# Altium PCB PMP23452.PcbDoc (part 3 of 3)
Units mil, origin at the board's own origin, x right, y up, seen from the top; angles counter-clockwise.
Board outline 4000 x 4000 mil, 6 copper layers (Top Layer, Layer 2, Layer 3, Layer 4, Layer 5, Bottom Layer), stack 40.224 mil thick; 235 components, 68 nets, 526 pads, 358 vias.
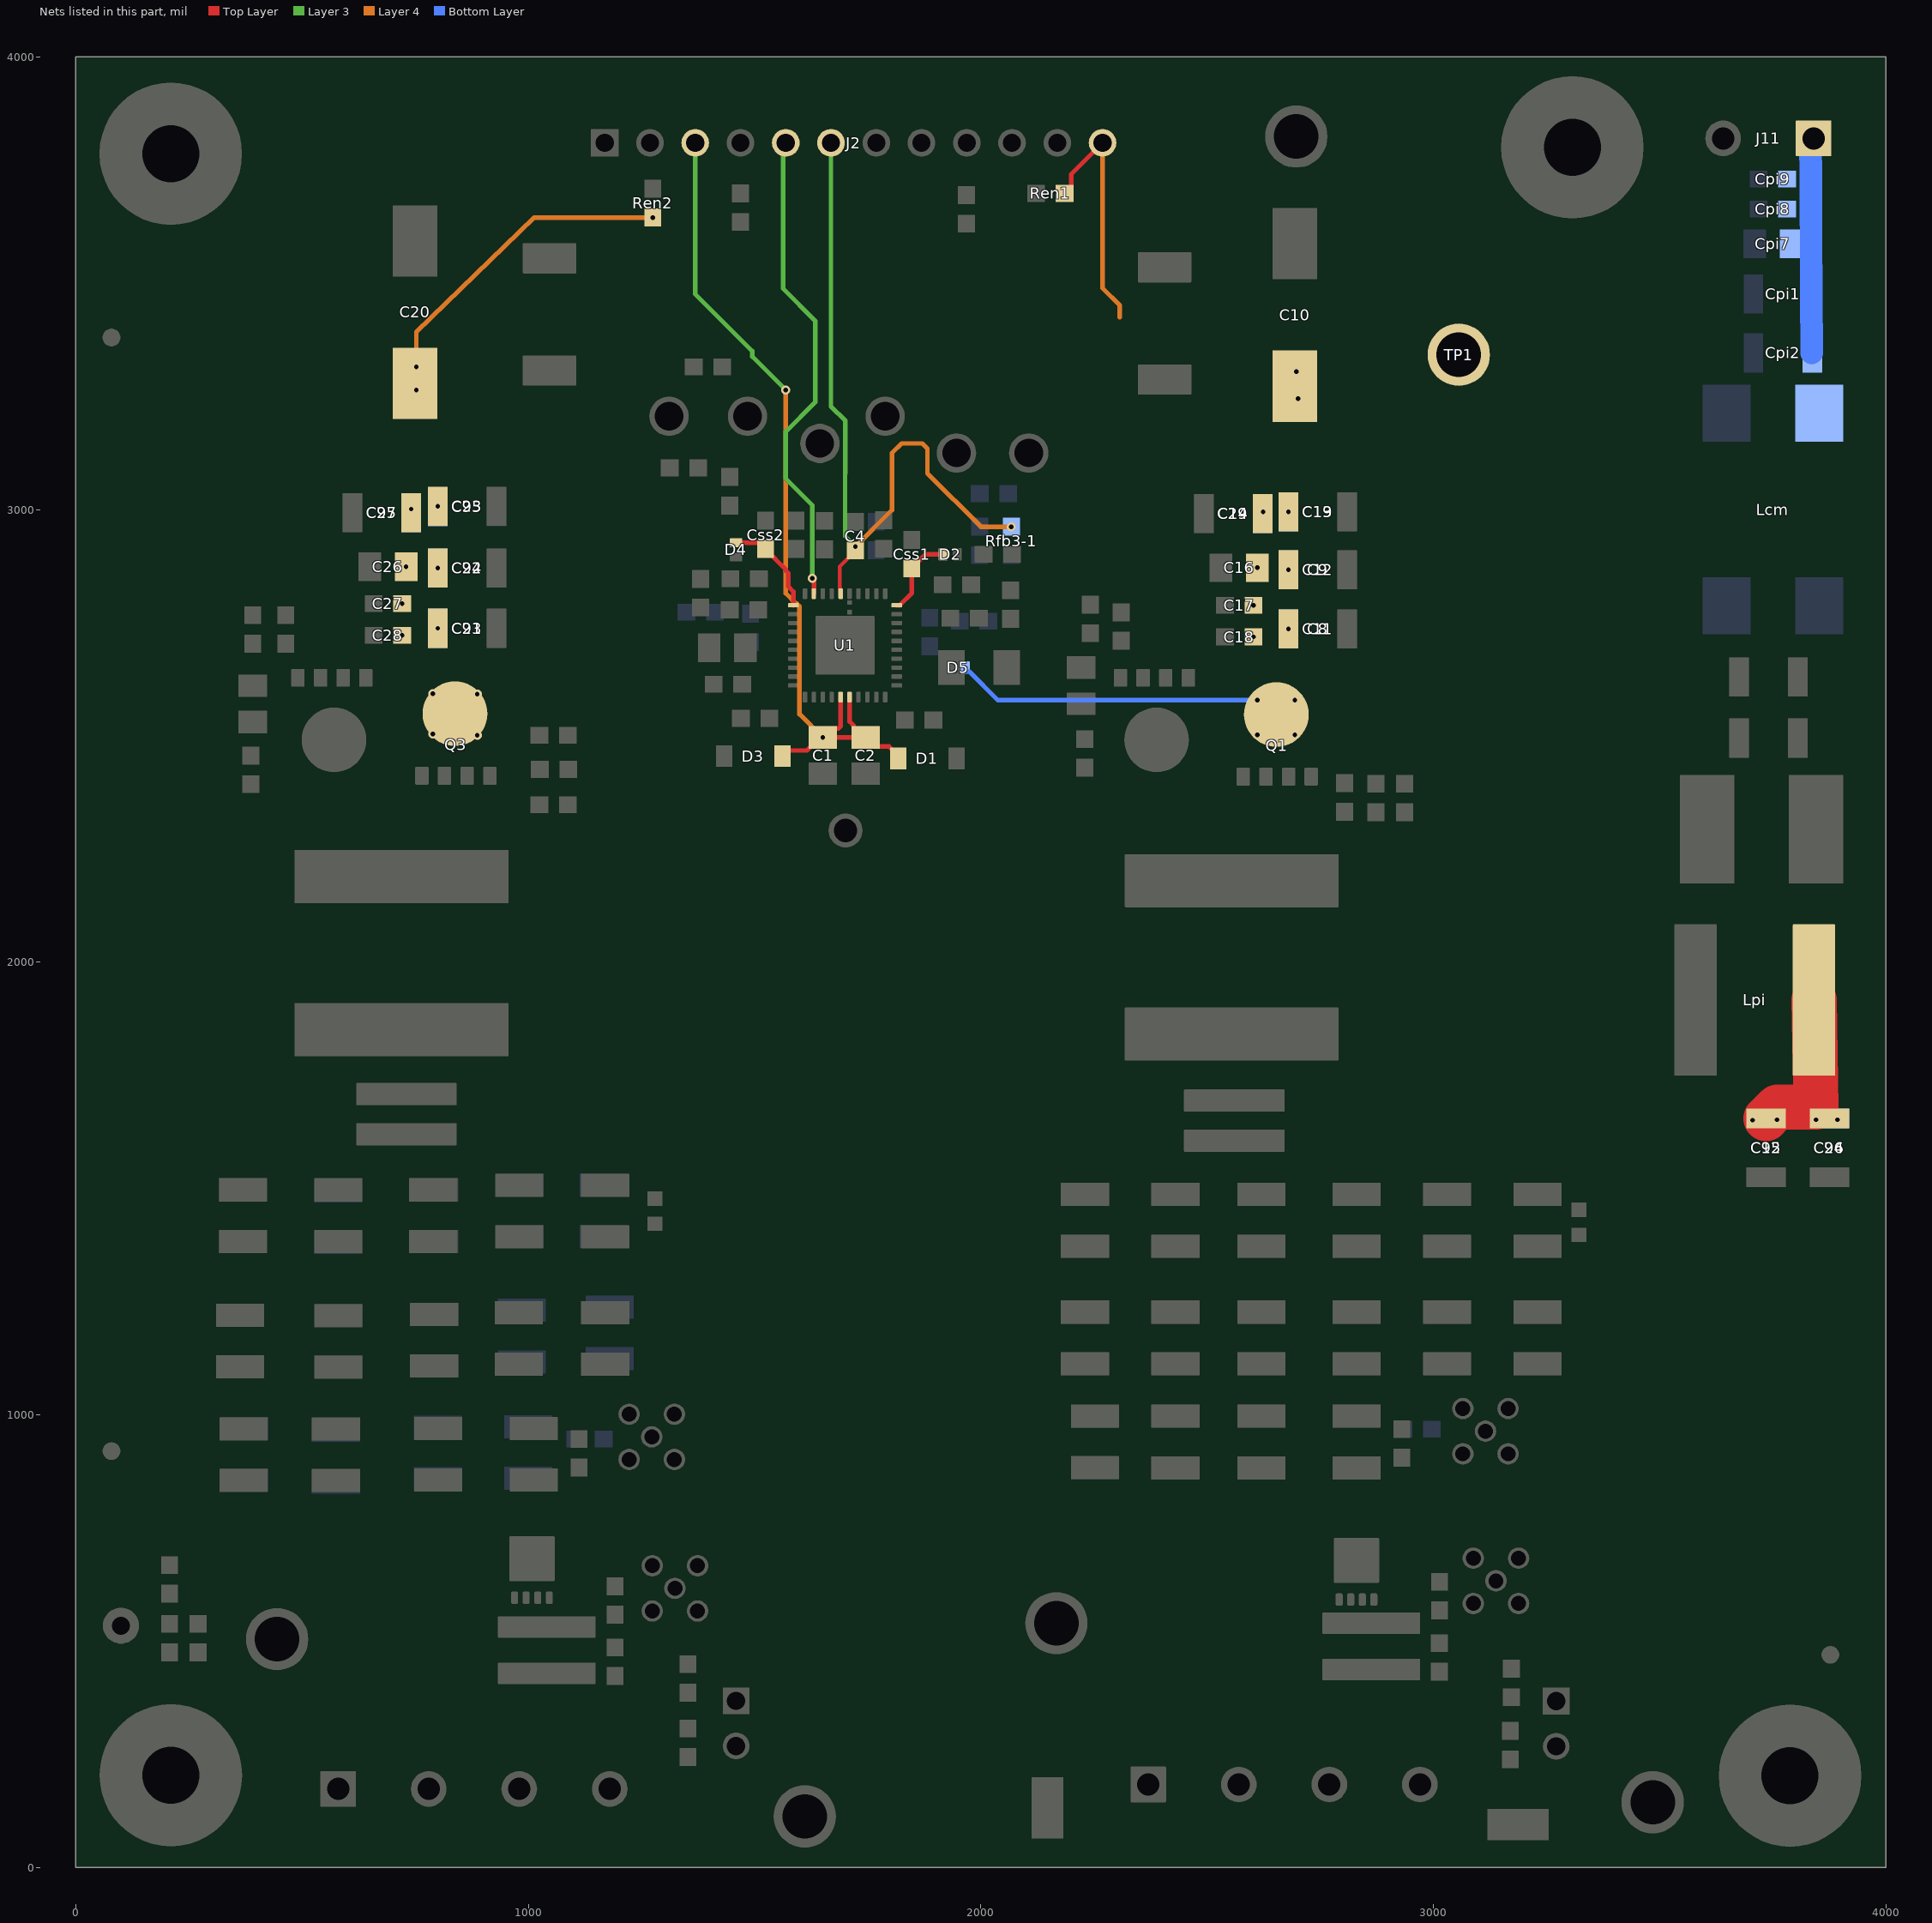
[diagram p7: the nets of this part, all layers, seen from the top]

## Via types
v1: diameter 20, hole 10, Top Layer to Bottom Layer, tented both sides, 332 vias
v2: diameter 19.68, hole 7.87, Top Layer to Bottom Layer, 24 vias
v3: diameter 19.68, hole 7.87, Top Layer to Bottom Layer, tented both sides, 2 vias

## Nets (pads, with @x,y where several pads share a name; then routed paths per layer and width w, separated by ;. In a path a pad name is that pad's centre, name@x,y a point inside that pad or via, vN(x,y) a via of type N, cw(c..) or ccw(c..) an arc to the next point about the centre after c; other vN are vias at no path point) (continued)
SS1: Css1.1 D2.1 U1.30 | length 181.6
  Top Layer w10: U1.30@1814.17,2788.58 1820.91,2788.58 1847.49,2815.17 Css1.1@1847.49,2869.76 1847.49,2870.74 1878.01,2901.25 D2.1@1916.5,2901.25
SS2: Css2.1 D4.1 U1.1 | length 220.9
  Top Layer w10: D4.1@1459.2,2926.84 1510.77,2926.84 1524.47,2913.14 Css2.1@1524.47,2912.71 1524.47,2911.73 1568.9,2867.29 1568.9,2865.31 1574.68,2859.53 1574.68,2829.67 1585.83,2818.52 U1.1@1585.83,2788.58
SYNCOUT: J2.5 U1.39 | length 1080.4
  Top Layer w10: v1(1627.52,2848.07) 1627.52,2845.37 1631.1,2841.79 U1.39@1631.1,2814.17
  Layer 3 w10: J2.5@1568.9,3810 1563,3804.1 1563,3488 1634,3417 1634,3237 1568.9,3171.9 1568.9,3068.36 1627.52,3009.73 v1(1627.52,2848.07)
VCC: C1.1 C2.1 D1.2 D3.2 J2.3 U1.15 U1.16 | length 1942.2
  Top Layer w10: D3.2@1561.67,2455.34 1574.01,2467.68 1615.51,2467.68 1644.29,2496.46 v1(1650.79,2496.46) ; U1.15@1690.16,2585.83 1690.16,2520.67 1685.95,2516.46 1670.79,2516.46 v1(1650.79,2496.46) ; U1.16@1709.84,2585.83 1709.84,2531.89 1718.78,2522.96 1718.78,2516.46 C2.1@1738.78,2496.46 ; D1.2@1817.2,2450.45 1817.2,2456.46 1797.2,2476.46 1765.28,2476.46 C2.1@1745.28,2496.46 C2.1@1738.78,2496.46 ; v1(1650.79,2496.46) C2.1@1738.78,2496.46
  Layer 3 w10: J2.3@1368.9,3810 1368.9,3476.02 1495,3349.92 1495,3338.02 v1(1568.9,3264.13)
  Layer 4 w10: v1(1568.9,3264.13) 1568.9,2815.08 1591.97,2792.01 1593.49,2792.01 1599.34,2786.15 1599.34,2547.9 v1(1650.79,2496.46)
VDDA: C4.2 J2.6 Rfb3-1.2 U1.36 | length 1646.2
  Top Layer w8: U1.36@1690.16,2814.17 1689.24,2815.09 1689.24,2827.03 1688.28,2827.98 1688.28,2874.36 C4.2@1722.64,2908.72
  Top Layer w10: C4.2@1722.64,2908.72 C4.2@1722.64,2909.7
  Layer 3 w10: J2.6@1668.9,3810 1668.9,3227.69 1700.66,3195.93 1700.66,3080.02 1700,3079.36 1700,2940.83 v1(1722.87,2917.96)
  Layer 4 w10: v1(1722.87,2917.96) 1803.81,2998.89 1803.81,3124.96 1824.85,3146 1870.6,3146 1882,3134.6 1882,3080 2000,2962 v1(2067,2962)
VIN: C8.1 C9.1 C10.1 C11.1 C12.1 C13.1 C14.1 C15.1 C16.1 C17.1 C18.1 C19.1 C20.1 C21.1 C22.1 C23.1 C24.1 C25.1 C26.1 C27.1 C28.1 C29.1 C92.1 C93.1 C94.1 C95.1 C96.1 C97.1 D5.2 J2.12 Lpi.2 Q1.5-6 Q3.5-6 Ren1.2 Ren2.2 TP1.1 | length 2284.2
  Top Layer w10: Ren1.2@2185,3698.5 2185.98,3698.5 2199.69,3712.2 2199.69,3740.79 J2.12@2268.9,3810
  Top Layer w100: C15.1@3735,1654.96 3760.04,1680 3845.47,1680 Lpi.2@3840.91,1916.5
  Layer 4 w10: v1(752.49,3315.13) 752.49,3392.49 1013,3645 v1(1275,3645) ; J2.12@2268.9,3810 2268.9,3489.1 2307,3451 2307,3425
  Bottom Layer w10: D5.2@1965.72,2650.87 1965.72,2646.93 1970.56,2642.09 1974.49,2642.09 2037.49,2579.09 v1(2610.71,2579.09)
  other v1: 3705,1651 3759,1652 3845.47,1652 3892.85,1652 887.24,2501.34 2610.71,2502.22 2693.94,2502.22 789,2504.06 2693.94,2579.09 887.24,2592.35 789,2593 2602.21,2718.7 721.5,2722.01 2679.65,2736.17 800.04,2737.49 2602.21,2788.58 721.5,2792.01 2679.65,2867.25 800.04,2870.74 2610.71,2871.5 730,2873.5 2623.85,2994.88 2679.65,2994.88 741.2,3001.18 800.04,3007.32 2700.75,3245 752.49,3264.13 2697,3304.44
VIN-ext: Cpi1.1 Cpi2.1 Cpi7.1 Cpi8.1 Cpi9.1 J11.1 Lcm.1 | length 479
  Bottom Layer w50: J11.1@3831,3832 J11.1@3831.08,3819.94 ; J11.1@3833.08,3812.94 3833.62,3729 3834.02,3667.54 3834.56,3585.71 3835.13,3496.99 3835.27,3475.99 Cpi2.1@3836.12,3345.99
pads on no net: FID1.1 FID2.1 FID3.1 H3.0 H4.0 H5.0 H6.0 H7.1 H8.1 H9.1 H10.1 Q100.9A Q100.9B Q100.9C Q100.9D Q200.9A Q200.9B Q200.9C Q200.9D

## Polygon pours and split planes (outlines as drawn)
VIN on Top Layer "TOP_LAYER_VIN_P000" (solid, remove dead copper, pour order 0): 2633.94,3367.93 2756.94,3367.93 2756.94,3077.09 2729.84,3050 2729.84,2687.43 2764.28,2653 2764.28,2464.05 2547.54,2464.05 2540.28,2471.32 2550.66,2481.7 2550.66,2660.44 2555.03,2660.44 2584.77,2690.18 2584.77,3054.77 2637.99,3108 2633.94,3112.05 2633.94,3371.26
VIN on Top Layer "TOP_LAYER_VIN_P005" (solid, remove dead copper, pour order 5): 670.53,3367.68 815,3367.68 815,3097.72 855,3057.72 855,2681.46 896.38,2640.08 947.28,2640.08 947.28,2475.28 944.18,2472.18 942.01,2474.36 729.84,2474.36 729.84,2656.3 735.82,2662.27 699.01,2699.08 699.01,2925 686.04,2937.97 676.24,2937.97 676.24,3361.97
5V on Top Layer "TOP_LAYER_5V_P009" (solid, remove dead copper, pour order 9): 290,1655 294,1659 1324,1659 1324,920.39 1040.91,637.3 904.36,545.31 904.36,41 400.05,41 400.05,685 288,685 286,683 286,1655
PGND on Top Layer "TOP_LAYER_PGND_P029" (solid, remove dead copper, pour order 29): 20,3980 20,20 3980,20 3980,3000 3500,3000 3500,3980
NetCpi3_1 on Top Layer "TOP_LAYER_NETCPI3_1_P028" (solid, remove dead copper, pour order 28): 3898.37,2695 3750.86,2695 3750,2694.14 3750,2170 3898.37,2170
NetC102_2 on Top Layer "TOP_LAYER_NETC102_2_P020" (solid, remove dead copper, pour order 20): 2720,623.66 2720,495.5 2956.56,495.5 2988.05,464.01 3037.89,464.01 3040.4,461.5 3040.4,599.88 2986.23,599.88 2964.87,578.52 2855.59,578.52 2855.59,623.66
NetC6_1 on Top Layer "TOP_LAYER_NETC6_1_P017" (solid, remove dead copper, pour order 17): 2282.74,2123 2286.74,2127 2803.74,2127 2803.74,2266.87 2711.99,2358.63 2711.99,2450.45 2526.63,2450.45 2521.74,2455.34 2530.29,2463.88 2530.29,2579.09 2281.98,2579.09 2265.22,2562.33 2265.22,2139.53 2282.74,2122
NetL1_1 on Top Layer "TOP_LAYER_NETL1_1_P012" (solid, remove dead copper, pour order 12): 2304.84,1914.5 2294.94,1904.59 2294.94,1755.41 2391.47,1658.87 2757.54,1658.87 2807.84,1709.18 2807.84,1916.5 2310.34,1916.5 2307.34,1913.5
3.3V on Top Layer "TOP_LAYER_3.3V_P011" (solid, remove dead copper, pour order 11): 2166.72,1648.5 2170.72,1652.5 3373,1652.5 3373,1086.17 2917.64,630.81 2700,630.81 2700,34.5 2052,34.5 2052,565.78 2052,1648.5
NetC202_2 on Top Layer "TOP_LAYER_NETC202_2_P010" (solid, remove dead copper, pour order 10): 950.84,616.8 950.84,576.78 936.58,576.78 918.28,558.48 918.28,488.63 1134.61,488.63 1166.1,457.14 1215.94,457.14 1218.45,454.63 1218.45,593.01 1164.28,593.01 1142.92,571.65 1025.97,571.65 1025.97,616.8 950.28,616.8
AGND on Top Layer "TOP_LAYER_AGND_P006" (solid, remove dead copper, pour order 6): 1349.68,2815.17 1471.01,2815.17 1471.01,2869.55 1472.2,2870.74 1468.62,2874.32 1430.9,2874.32 1430.9,2941.86 1432.74,2943.7 1434.67,2941.77 1808.27,2941.77 1808.27,2935.78 1820.91,2923.14 1820.91,2897.32 1824.84,2901.25 1895.29,2901.25 1895.29,2920.43 1916.62,2941.77 1968.9,2941.77 1968.9,2870.74 1949.97,2851.81 1949.97,2797.68 1952.92,2794.73 2117.91,2794.73 2117.91,2857.6 2105.76,2869.76 2038.23,2869.76 2038.23,3162.47 1960.81,3295.16 1235,3365 1337.18,2814.09 1329.88,2806.8 1329.88,2802.11 1329.88,2810.92 1327.81,2808.86
NetL2_2 on Top Layer "TOP_LAYER_NETL2_2_P008" (solid, remove dead copper, pour order 8): 474,1915 464.09,1905.09 464.09,1755.91 560.63,1659.37 926.69,1659.37 977,1709.68 977,1917 479.5,1917 476.5,1914
NetC7_1 on Top Layer "TOP_LAYER_NETC7_1_P007" (solid, remove dead copper, pour order 7): 458,2123 462,2127 979,2127 979,2266.87 887.24,2358.63 887.24,2450.45 701.89,2450.45 697,2455.34 705.54,2463.88 705.54,2579.09 457.24,2579.09 440.47,2562.33 440.47,2139.53 458,2122
AGND on Layer 2 "LAYER_2_AGND_P002" (solid, remove dead copper, pour order 2): 1595.4,3186.91 1595.4,2965.95 1803.81,2965.95 1811.23,2973.37 1811.23,3246.48 1654.96,3246.48
PGND on Layer 2 "LAYER_2_PGND_P036" (solid, remove dead copper, pour order 36): 20,3980 20,20 3980,20 3980,3000 3500,3000 3500,3980
AGND on Layer 2 "LAYER_2_AGND_P001" (solid, remove dead copper, pour order 1): 1368.9,3025.47 1463.53,3025.47 1495,2994 1826.58,2994 2007,2958 2060.18,2857.44 2060.18,2846.9 2027.43,2810.44 1368.9,2810.44
VIN on Bottom Layer "BOTTOM_LAYER_VIN_P015" (solid, remove dead copper, pour order 15): 823,3367.68 823,2777.48 949.25,2470.06 758.7,2470.06 703.08,2698 705.54,2700.47 705.54,3367.68
VIN on Bottom Layer "BOTTOM_LAYER_VIN_P016" (solid, remove dead copper, pour order 16): 2721.01,3363.95 2721.01,2476.51 2586.71,2476.51 2586.71,3363.95
PGND on Bottom Layer "BOTTOM_LAYER_PGND_P031" (solid, remove dead copper, pour order 31): 20,3980 20,20 3980,20 3980,3000 3500,3000 3500,3980
NetCpi3_1 on Bottom Layer "BOTTOM_LAYER_NETCPI3_1_P030" (solid, remove dead copper, pour order 30): 3913.39,2880 3750.86,2880 3750,2879.14 3750,2430 3913.39,2430
PGND-ext on Bottom Layer "BOTTOM_LAYER_PGND-EXT_P025" (solid, remove dead copper, pour order 25): 3739.11,3880 3739.11,3531.12 3762.62,3507.61 3762.62,3290.88 3760.88,3290.88 3730,3260 3730,3120 3580,3120 3580,3880
VIN-ext on Bottom Layer "BOTTOM_LAYER_VIN-EXT_P014" (solid, remove dead copper, pour order 14): 3920,3880 3920,3120 3770,3120 3770,3264.31 3796.57,3290.88 3800,3290.88 3800,3503.32 3760,3543.32 3760,3880
PGND on Layer 4 "LAYER_4_PGND_P038" (solid, remove dead copper, pour order 38): 20,3980 20,20 3980,20 3980,3000 3500,3000 3500,3980
3.3V on Layer 4 "LAYER_4_3.3V_P024" (solid, remove dead copper, pour order 24): 3373,1560 3373,1081.75 2917.64,626.38 2700,626.38 2700,30.08 2052,30.08 2052,561.36 2052,1560
5V on Layer 4 "LAYER_4_5V_P022" (solid, remove dead copper, pour order 22): 1255,1600 1255,838.51 1026.79,610.29 835.46,610.29 835.46,545.58 848.6,476.66 848.6,387.27 848.6,0.86 835.46,13.99 385.92,13.99 385.92,657.99 273.87,657.99 271.87,655.99 271.87,1600
VIN on Layer 4 "LAYER_4_VIN_P019" (solid, remove dead copper, pour order 19): 3050.02,2550 3050.02,1950 3170,1950 3520,1600 3950,1600 3950,1750 3930,1770 3780,1770 3317.52,2232.48 3317.52,2550 3166,2550
VIN on Layer 4 "LAYER_4_VIN_P004" (solid, remove dead copper, pour order 4): 939.51,2461.34 675.25,2461.34 675.25,3342.25 1016,3683 1021,3678 1332,3678 2519.27,3678 2874.73,3448 2985,3448 3310,3448 3310,2605 3310,2391.24 2516,2391.24 2516,2704.07 2565.08,2753.15 2565.08,3023.35 2249.43,3339 1004,3339 1004,2566.06 949.25,2511.31 949.25,2477.42 939.51,2467.68
PGND on Layer 3 "LAYER_3_PGND_P037" (solid, remove dead copper, pour order 37): 20,3980 20,20 3980,20 3980,3000 3500,3000 3500,3980
VIN on Layer 3 "LAYER_3_VIN_P033" (solid, remove dead copper, pour order 33): 2633.94,3363.95 2637.92,3367.93 2756.94,3367.93 2756.94,2471.39 2758.33,2470 2569.9,2470 2569.9,3148.86 2633.94,3212.91 2633.94,3369.6
VIN on Layer 3 "LAYER_3_VIN_P032" (solid, remove dead copper, pour order 32): 681.14,3365 686.04,3360.1 686.04,2700 741.2,2644.84 741.2,2478.99 742.76,2477.42 923.63,2477.42 921.83,2479.22 921.83,2623.8 845.63,2700 845.63,3365 691.32,3365 676.24,3349.92
3.3V on Layer 3 "LAYER_3_3.3V_P023" (solid, remove dead copper, pour order 23): 2162.75,1644.08 2166.75,1648.08 3369.02,1648.08 3369.02,1081.75 2913.66,626.38 2696.02,626.38 2696.02,30.08 2048.02,30.08 2048.02,561.36 2048.02,1644.08
5V on Layer 3 "LAYER_3_5V_P021" (solid, remove dead copper, pour order 21): 290,1655 294,1659 1324,1659 1324,920.39 1040.91,637.3 880,637.3 880,603 862.72,503.67 862.72,414.28 862.72,27.87 849.59,41 400.05,41 400.05,685 288,685 286,683 286,1655
VIN on Layer 5 "LAYER_5_VIN_P034" (solid, remove dead copper, pour order 34): 2553.62,2633.27 2552.34,2631.98 2552.34,2448.03 2750.2,2448.03 2751.93,2449.76 2751.93,2631.1 2555.78,2631.1
VIN on Layer 5 "LAYER_5_VIN_P027" (solid, remove dead copper, pour order 27): 741.2,2644.84 739.92,2643.56 739.92,2459.61 937.77,2459.61 939.51,2461.34 939.51,2642.68 743.36,2642.68
PGND on Layer 5 "LAYER_5_PGND_P035" (solid, remove dead copper, pour order 35): 20,3980 20,20 3980,20 3980,3000 3500,3000 3500,3980

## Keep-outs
Keep-Out Layer:
  text ".Layer_Name" at 577,-858.49 h60

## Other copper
Top Layer:
  text ".Layer_Name" at 577,-858.49 h60
Bottom Layer:
  text ".Layer_Name" at 577,-858.49 h60

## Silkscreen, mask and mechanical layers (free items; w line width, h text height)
Top Overlay:
  text "EN1" at 2081.24,3894 h30 r90
  text "PG1" at 1972.42,3890.81 h30 r90
  text "VCC" at 1334.48,3888 h30
  text "Vin" at 2243.88,3888 h30
  text "PGND" at 1086,3882 h30
  text "EN2" at 1227.83,3882 h30
  text "PGND" at 2105.91,3882 h30
  text "PG2" at 1484.78,3876 h30 r90
  text "sync" at 1574.06,3876 h25 r90
  text "VDDA" at 1682.28,3876 h25 r90
  text "DEMB" at 1773.63,3876 h25 r90
  text "AGND" at 1876.64,3876 h25 r90
  text "-" at 3600,3550.01 h60
  text "+" at 3834.62,3541.67 h50
  text "Vin-ext" at 3610,3460 h50
  text "Bode plot interfaces" at 1405.74,3456 h30
  text "Vin" at 3122.67,3411.27 h50
  text "inj-2" at 1295,3293.04 h30 r90
  text "Vout2" at 1510.4,3293.04 h30 r90
  text "gnd1" at 1769.28,3293.04 h30 r90
  text "gnd2" at 1655.46,3280.25 h30 r90
  text "inj-1" at 1960.54,3266.18 h30 r90
  text "Vout1" at 2082.39,3235.82 h30 r90
  text "Input EMI filter" at 3543.34,2560.12 h50 r90
  text "Caution: High Temperatures" at 1018,1938.16 h50
  text "Vsense" at 3223.26,973.3 h30
  text "Vsense" at 1373.62,937.81 h30
  text "Isense" at 1426,626 h30
  text "Isense" at 3237.75,616.55 h30
  text "Vout2 sns" at 134,601.96 h30 r90
  text "+" at 2237,593.88 h50
  text "+" at 481.9,581.49 h50
  text "Vout1" at 2335.91,528.61 h50
  text "Vout2" at 570,488.56 h50
  text "sig gen" at 3343,416.59 h30
  text "+" at 2348.33,403.13 h50
  text "+" at 2550.05,403.13 h50
  text "+" at 555.05,391.17 h50
  text "+" at 753.75,387.42 h50
  text "sig gen" at 1586,374.01 h30
  text "+" at 1530.05,358.88 h50
  text "-" at 2737.51,357.44 h80
  text "-" at 2909.7,355.27 h80
  text "+" at 3349,349.47 h50
  text "-" at 949.79,348.46 h80
  text "-" at 1098.16,348.46 h80
  text "-" at 3349,233.8 h80
  text "-" at 1531.58,222.32 h80
  text "+" at 2130,220.18 h50
  text "-" at 3291.58,10.8 h80
  text ".Layer_Name" at 577,-858.49 h60
Bottom Overlay:
  text "'.PRJ_Number'.PCB_Rev" at 2165,319 h108.27
  text ".Layer_Name" at 577,-858.49 h60
Top Paste:
  text ".Layer_Name" at 577,-858.49 h60
Bottom Paste:
  text ".Layer_Name" at 577,-858.49 h60
Top Solder:
  text ".Layer_Name" at 577,-858.49 h60
  text ".Layer_Name" at 577,-858.49 h60
Bottom Solder:
  text ".Layer_Name" at 577,-858.49 h60
Drill Guide:
  text ".Layer_Name" at 577,-858.49 h60
M1 Board Outline:
  lines w10: 0,0 0,4000 4000,4000 4000,0 0,0
  lines w20: -10,0 ccw(c0,0) 0,-10 ; -10,0 ccw(c0,0) 0,-10 ; -10,0 -10,4000 ; -10,4000 cw(c0,4000) 0,4010 ; -10,4000 cw(c0,4000) 0,4010 ; 0,-10 4000,-10 ; 0,4010 4000,4010 ; 4000,-10 ccw(c4000,0) 4010,0 ; 4000,-10 ccw(c4000,0) 4010,0 ; 4000,4010 cw(c4000,4000) 4010,4000 ; 4000,4010 cw(c4000,4000) 4010,4000 ; 4010,0 4010,4000 ; 10,10 10,3990 3990,3990 3990,10 10,10
  text ".Layer_Name" at 577,-858.49 h60
M2 Board Dimensions:
  rectangle: 0,-275 125,-150
  rectangle: 125,-400 500,-275
  lines w7: 0,-275 1000,-275 ; 125,-400 125,-150 ; 250,-400 250,-150 ; 500,-400 500,-150 ; 750,-400 750,-150 ; 0,-400 1000,-400 1000,-150 0,-150 0,-400
  text ".Layer_Name" at 577,-858.49 h60
M3 3D STEP Top:
  text ".Layer_Name" at 577,-858.49 h60
M4 3D STEP Bottom:
  text ".Layer_Name" at 577,-858.49 h60
M5 Assembly Top:
  lines w10: -292,-930.17 6308,-930.17 ; -292,-726.83 6310,-726.83 ; -292,-523.5 -292,-1133.5 3713,-1133.5 6310,-1133.5 6310,-523.5 -291.5,-523.5 -291.5,-1133.5 1284,-1133.5 ; 2173,-1133.5 2173,-523.5 ; 3440,-726.83 3440,-523.5 ; 4280,-726.83 4280,-523.5 ; 4902,-1140 4902,-937.17
  text "COMPONENTS MARKED 'DNP' SHOULD NOT BE POPULATED." at 1153.5,-318.5 h60
  text "ASSEMBLY VARIANT:" at 1153,-434 h60
  text ".VariantName" at 2189,-434 h60
  text "PCB VIEWED FROM TOP SIDE" at -228.5,-655.67 h60
  text "BOARD #:" at 2248,-655.67 h60
  text ".PRJ_Number" at 2793.5,-655.67 h60
  text "REV:" at 3638,-655.67 h60
  text ".PCB_Rev" at 3929.5,-655.67 h60
  text "SVN REV:" at 4476,-655.67 h60
  text ".VersionControl_RevNumber" at 4982,-655.67 h60
  text "TID #:" at 2248,-859 h60
  text ".TID" at 2793.5,-859 h60
  text "PLOT NAME =" at -228.5,-1064.34 h60
  text ".plot_File_Name" at 577,-1064.34 h60
  text "GENERATED    :" at 2250,-1064.34 h60
  text ".Print_Date" at 3119.5,-1064.34 h60
  text ".Print_Time" at 3848.5,-1064.34 h60
  text "TEXAS INSTRUMENTS" at 5113,-1064.34 h60
M6 Assembly Bottom:
  lines w10: -292.5,-727.33 6309.5,-727.33 ; -290.5,-930.67 6309.5,-930.67 ; 1115.5,-1140.5 1115.5,-937.67 ; 1737.5,-727.33 1737.5,-524 ; 2577.5,-727.33 2577.5,-524 ; 3844.5,-1134 3844.5,-524 ; 4733.5,-1134 6309,-1134 6309,-524 -292.5,-524 -292.5,-1134 2304.5,-1134 6309.5,-1134 6309.5,-524
  text "COMPONENTS MARKED 'DNP' SHOULD NOT BE POPULATED." at 6102,-318 h60
  text ".VariantName" at 5058,-434 h60
  text "ASSEMBLY VARIANT:" at 6097,-434 h60
  text ".VersionControl_RevNumber" at 1035.5,-656.17 h60
  text "SVN REV:" at 1541.5,-656.17 h60
  text ".PCB_Rev" at 2088,-656.17 h60
  text "REV:" at 2379.5,-656.17 h60
  text ".PRJ_Number" at 3224,-656.17 h60
  text "BOARD #:" at 3769.5,-656.17 h60
  text "PCB VIEWED FROM BOTTOM SIDE" at 6246,-656.17 h60
  text ".TID" at 3224,-859.5 h60
  text "TID #:" at 3769.5,-859.5 h60
  text "TEXAS INSTRUMENTS" at 904.5,-1064.84 h60
  text ".Print_Time" at 2169,-1064.84 h60
  text ".Print_Date" at 2898,-1064.84 h60
  text "GENERATED    :" at 3767.5,-1064.84 h60
  text ".plot_File_Name" at 5440.5,-1064.84 h60
  text "PLOT NAME =" at 6246,-1064.84 h60
M9 Title Sheet:
  drawing of 57 lines, arcs and shapes, not listed
  text "1" at 739.84,8036.5 h70
  text "2" at 3235.5,8036.5 h70
  text "3" at 5724.84,8036.5 h70
  text "4" at 8231.51,8036.5 h70
  text "5" at 10730.5,8036.5 h70
  text "6" at 13235.5,8036.5 h70
  text "A" at -416.5,6893.5 h70
  text "A" at 14383.5,6893.5 h70
  text "B" at -416.5,4513.5 h70
  text "B" at 14383.5,4513.5 h70
  text "C" at -416.5,2138.5 h70
  text "C" at 14383.5,2138.5 h70
  text "PROJECT TITLE:" at 11343.5,277.5 h45
  text ".PRJ_Title" at 11393.5,144.17 h70
  text "DESIGNED FOR:" at 11343.5,-23.5 h45
  text ".PRJ_Customer" at 11393.5,-163.5 h70
  text "D" at -416.5,-231.5 h70
  text "D" at 14383.5,-231.5 h70
  text "FILE NAME:" at 11343.5,-323.5 h45
  text ".PCB_File_Name_No_Path" at 11393.5,-443.5 h70
  text "Texas Instruments (TI) and/or its licensors do not warrant the accuracy or completeness of this specification" at 6374,-605.34 h45
  text "ENGINEER:" at 11343.5,-613.5 h45
  text "LAYOUT BY:" at 12848.5,-613.5 h45
  text "or any information contained therein. TI and/or its licensors do not warrant that this design will meet" at 6329.01,-718 h45
  text ".PRJ_Engineer" at 11393.5,-768.49 h70
  text ".PCB_Layout" at 12899,-768.49 h70
  text "the specifications, will be suitable for your application or fit for any particular purpose, or will operate in" at 6329.01,-830.67 h45
  text ".Layer_Name" at 577,-858.49 h60
  text "ALTIUM DESIGNER VERSION:" at 12848.5,-923.5 h45
  text "an implementation. TI and/or its licensors do not warrant that the design is production worthy. You should" at 6329.01,-943.33 h45
  text "completely validate and test your design implementation to confirm the system functionality for your application." at 6374,-1056 h45
  text ".print_Scale" at 11393.5,-1056.83 h70
  text ".Application_BuildNumber" at 12899,-1056.83 h70
  text "1" at 739.84,-1263.5 h70
  text "2" at 3235.5,-1263.5 h70
  text "3" at 5724.84,-1263.5 h70
  text "4" at 8231.51,-1263.5 h70
  text "5" at 10730.5,-1263.5 h70
  text "6" at 13235.5,-1263.5 h70
M10 Fab Notes:
  drawing of 189 lines, arcs and shapes, not listed
  text "DESIGN INFORMATION" at 12382.02,6356.17 h60
  text "MIN. TRACK WIDTH:" at 11737.46,6224.05 h60
  text "8" at 12833.7,6224.05 h60
  text "MIL" at 12988.46,6224.05 h60
  text "7.874" at 12667.32,6102.36 h60
  text "MIN. CLEARANCE:" at 11737.46,6099.92 h60
  text "MIL" at 12988.46,6099.92 h60
  text "MIN. VIA PAD SIZE:" at 11737.46,5975.8 h60
  text "24" at 12803.71,5975.8 h60
  text "MIL" at 12988.46,5975.8 h60
  text "0.05mm (2MIL)" at 12432.46,5845.9 h60
  text "MINIMUM ANNULAR RING" at 11408.23,5837.67 h60
  text "EXTERNAL" at 13140.46,5837.67 h60
  text "PER" at 11608.23,5727.55 h60
  text "IPC-D-275 CLASS 2 LEVEL C" at 11828.23,5727.54 h60
  text "MIL, HOLES" at 13316.46,5627.07 h60
  text "+/-" at 12924,5618.48 h60
  text "+/-" at 13778,5618.48 h60
  text "REGISTRATION TOLERANCES:" at 11408.23,5617.42 h60
  text "METAL" at 12608,5617.42 h60
  text "5" at 13184.2,5617.42 h60
  text "3" at 14017.2,5617.42 h60
  text "MIL" at 14133.46,5617.42 h60
  text "HOLE SIZE TOLERANCE (UNLESS OTHERWISE SPECIFIED):" at 11408.23,5519.1 h60
  text "+/-" at 13778,5516.23 h60
  text "3" at 14017.2,5515.17 h60
  text "MIL" at 14133.46,5515.17 h60
  text "MATERIAL:" at 11333.46,5377.52 h60
  text "FR-4 High Tg" at 12319.9,5249 h60
  text "X" at 12175.46,5241.01 h60
  text "FR-4" at 11754.46,5236.49 h60
  text "OTHER" at 13242.46,5236.49 h60
  text "62 MIL (1.6mm) +/-10%" at 12074.56,5093.46 h60
  text "X" at 11954.46,5091.01 h60
  text "THICKNESS:" at 11408.23,5085.24 h60
  text "OTHER" at 13359.46,5085.24 h60
  text "TOLERANCE:" at 11408.23,4946.92 h60
  text "X" at 12256.46,4946.92 h60
  text "ANSI IPC-6012 TYPE 3 CLASS 2" at 12434.48,4946.92 h60
  text "OTHER +/-" at 12434.46,4802.73 h60
  text "BOW & TWIST:" at 11408.23,4657.54 h60
  text "X" at 12256.46,4657.54 h60
  text "ANSI IPC-6012 TYPE 3 CLASS 2" at 12434.48,4657.54 h60
  text "OTHER +/-" at 12434.46,4510.85 h60
  text "DRILLING:" at 11333.46,4380.23 h60
  text "NC_DRILL FILES" at 13094.46,4275.04 h60
  text "REFERENCE:" at 11408.23,4271.1 h60
  text "X" at 12065.46,4271.01 h60
  text "AS SHOWN" at 12243.46,4271.1 h60
  text "X" at 12966.46,4271.1 h60
  text "OTHER" at 13392.46,4128.85 h60
  text "PTH COPPER THICKNESS:" at 11407.91,4125.32 h60
  text "X" at 12547.14,4125.32 h60
  text "20-30 um" at 12675.14,4125.32 h60
  text "BOARD FINISH:" at 11333.46,3977.73 h60
  text "SILKSCREEN:" at 11488.68,3867.6 h60
  text "X" at 12446.46,3867.6 h60
  text "TOP" at 12563.46,3867.6 h60
  text "X" at 12956.46,3867.6 h60
  text "BOTTOM" at 13074.46,3867.6 h60
  text "SILKSCREEN COLOR:" at 11488.68,3712.41 h60
  text "X" at 12445.46,3712.41 h60
  text "WHITE" at 12563.46,3712.41 h60
  text "OTHER" at 13074.46,3712.41 h60
  text "X" at 12576.46,3568.96 h60
  text "GREEN" at 12694.46,3568.96 h60
  text "OTHER" at 13312.46,3568.96 h60
  text "SOLDER RESIST COLOR:" at 11488.68,3562.1 h60
  text "X" at 12576.46,3414.71 h60
  text "MATTE" at 12694.46,3414.71 h60
  text "SEMI-GLOSS" at 13312,3414.07 h60
  text "IMMERSION GOLD (ENIG)" at 12394.46,3241.94 h60
  text "ENEPIG" at 13732,3234.72 h60
  text "SURFACE FINISH:" at 11333.46,3233.72 h60
  text "X" at 12216.46,3233.72 h60
  text "IMM. TIN/SILVER OR EQUIV" at 11663,3096.4 h60
  text "OTHER" at 13094.46,3092.47 h60
  text "ARRAY/PANEL:" at 11333.46,2937.09 h60
  text "CUT AND TRIM PER M1 BOARD OUTLINE" at 12394.46,2928.87 h60
  text "N.C. ROUTE" at 12394.46,2792.9 h60
  text "X" at 13082.46,2792.9 h60
  text "V. SCORE" at 13260.46,2792.9 h60
  text "CERTIFICATION:" at 11333.46,2663.77 h60
  text "MATERIALS AND WORKMANSHIP FOR ALL PCBS" at 12058.46,2663.77 h60
  text "TO MEET OR EXCEED THE REQUIREMENTS OF:" at 12058.46,2569.71 h60
  text "X" at 11695.97,2441.08 h60
  text "ANSI IPC-A-600F CLASS ->" at 11823.96,2441.08 h60
  text "X" at 13471.97,2441.08 h60
  text "2" at 13581.96,2441.08 h60
  text "1" at 13266.96,2439.58 h60
  text "3" at 13935.96,2439.58 h60
  text "X" at 12507.97,2293.39 h60
  text "RoHS" at 12635.96,2293.39 h60
  text "OTHER" at 13280.36,2293.39 h60
  text "PER ORDER" at 13677.42,2293.39 h60
  text "ALL BOARDS MUST MEET OR EXCEED UL94-V0 REQUIREMENTS." at 11361,2139.57 h60
  text "PCB MUST BEAR THE UL94V-0 UL REGISTERED MATERIAL ID NUMBER" at 11361,2023.5 h60
  text "ADDITIONAL REQUIREMENTS:" at 11333.46,1854.08 h60
  text "MICROSECTION:" at 11408.23,1746.95 h60
  text "YES" at 12313.96,1746.95 h60
  text "REQUIRED" at 13175.46,1602.62 h60
  text "BARE BOARD ELEC. TEST:" at 11408.23,1599.76 h60
  text "NONE" at 12713.96,1599.76 h60
  text "X" at 13057.46,1599.76 h60
  text "PER ORDER" at 13767.46,1599.76 h60
  text "XX MIL VIAS REQUIRE NON-CONDUCTIVE FILL AND PLANARIZE" at 11576.38,1394.82 h59
  text "XX MIL VIAS REQUIRE CONDUCTIVE FILL AND PLANARIZE" at 11584.38,1290.84 h60
  text "OUTER XX MIL TRACES REQUIRE 50 OHM SINGLE-ENDED IMPEDANCE" at 11583.39,1127.46 h58
  text "LAYER 2 & 3 (INNER LAYERS) XX MIL WIDE, XX MIL SPACE / TRACES REQUIRE 100 OHM DIFFERENTIAL IMPEDANCE" at 11575.39,891.74 h60
  text ".Layer_Name" at 577,-858.49 h60
M11 Gerber Information:
  lines w10: -292,-930.17 6308,-930.17 ; -292,-726.83 6310,-726.83 ; -292,-523.5 -292,-1133.5 3713,-1133.5 6310,-1133.5 6310,-523.5 -291.5,-523.5 -291.5,-1133.5 1284,-1133.5 ; 2173,-1133.5 2173,-523.5 ; 3440,-726.83 3440,-523.5 ; 4280,-726.83 4280,-523.5 ; 4902,-1140 4902,-937.17
  text "ALL ARTWORK VIEWED FROM TOP SIDE" at -228.5,-655.67 h60
  text "BOARD #:" at 2248,-655.67 h60
  text ".PRJ_Number" at 2793.5,-655.67 h60
  text "REV:" at 3638,-655.67 h60
  text ".PCB_Rev" at 3929.5,-655.67 h60
  text "SVN REV:" at 4476,-655.67 h60
  text ".VersionControl_RevNumber" at 4982,-655.67 h60
  text "LAYER NAME =" at -228.5,-858.49 h60
  text "TID #:" at 2248,-859 h60
  text ".TID" at 2793.5,-859 h60
  text "PLOT NAME =" at -228.5,-1064.34 h60
  text ".plot_File_Name" at 577,-1064.34 h60
  text "GENERATED    :" at 2250,-1064.34 h60
  text ".Print_Date" at 3119.5,-1064.34 h60
  text ".Print_Time" at 3848.5,-1064.34 h60
  text "TEXAS INSTRUMENTS" at 5113,-1064.34 h60
M12 Stackup:
  drawing of 264 lines, arcs and shapes, not listed
  text "Layer" at 5465.76,6750.01 h60
  text "Name" at 5716.86,6750.01 h60
  text "Material" at 6202.43,6750.01 h60
  text "Thickness" at 6638.78,6750.01 h60
  text "Constant" at 6997.21,6750.01 h60
  text "Board Layer Stack" at 7328.94,6750.01 h60
  text "Top Overlay" at 5716.86,6630.01 h60
  text "Top Solder" at 5716.86,6510.01 h60
  text "Solder Resist" at 6202.43,6510.01 h60
  text "0.40mil" at 6638.78,6510.01 h60
  text "3.5" at 6997.21,6510.01 h60
  text "1" at 5465.76,6390.01 h60
  text "Top Layer" at 5716.86,6390.01 h60
  text "2.10mil" at 6638.73,6390.01 h60
  text "Dielectric 1" at 5716.86,6270.01 h60
  text "PP-006" at 6202.43,6270.01 h60
  text "5.00mil" at 6638.78,6270.01 h60
  text "4.1" at 6997.21,6270.01 h60
  text "2" at 5465.71,6150.01 h60
  text "Layer 2" at 5716.86,6150.01 h60
  text "CF-004" at 6202.43,6150.01 h60
  text "2.76mil" at 6638.73,6150.01 h60
  text "Dielectric 2" at 5716.86,6030.01 h60
  text "PP-006" at 6202.43,6030.01 h60
  text "5.00mil" at 6638.78,6030.01 h60
  text "4.1" at 6997.21,6030.01 h60
  text "3" at 5465.76,5910.01 h60
  text "Layer 3" at 5716.86,5910.01 h60
  text "CF-004" at 6202.43,5910.01 h60
  text "2.76mil" at 6638.73,5910.01 h60
  text "Dielectric1" at 5716.86,5790.01 h60
  text "FR-4 High Tg" at 6202.43,5790.01 h60
  text "5.00mil" at 6638.78,5790.01 h60
  text "4.8" at 6997.21,5790.01 h60
  text "4" at 5465.76,5670.01 h60
  text "Layer 4" at 5716.86,5670.01 h60
  text "CF-004" at 6202.43,5670.01 h60
  text "2.76mil" at 6638.73,5670.01 h60
  text "Dielectric 3" at 5716.86,5550.01 h60
  text "PP-006" at 6202.43,5550.01 h60
  text "5.00mil" at 6638.78,5550.01 h60
  text "4.1" at 6997.21,5550.01 h60
  text "5" at 5465.76,5430.01 h60
  text "Layer 5" at 5716.86,5430.01 h60
  text "CF-004" at 6202.43,5430.01 h60
  text "2.76mil" at 6638.73,5430.01 h60
  text "Dielectric 4" at 5716.86,5310.01 h60
  text "PP-006" at 6202.43,5310.01 h60
  text "5.00mil" at 6638.78,5310.01 h60
  text "4.1" at 6997.21,5310.01 h60
  text "6" at 5465.76,5190.01 h60
  text "Bottom Layer" at 5716.86,5190.01 h60
  text "2.10mil" at 6638.73,5190.01 h60
  text "Bottom Solder" at 5716.86,5070.01 h60
  text "Solder Resist" at 6202.43,5070.01 h60
  text "0.40mil" at 6638.78,5070.01 h60
  text "3.5" at 6997.21,5070.01 h60
  text "Bottom Overlay" at 5716.86,4950.01 h60
  text ".Layer_Name" at 577,-858.49 h60
M13 Component Bodies Top:
  text ".Layer_Name" at 577,-858.49 h60
M14 Component Bodies Bottom:
  text ".Layer_Name" at 577,-858.49 h60
M15 Courtyards Top:
  text ".Layer_Name" at 577,-858.49 h60
M16 Courtyards Bottom:
  text ".Layer_Name" at 577,-858.49 h60
Drill Drawing:
  circle w10: c5363.72,3041.64 r27.63
  circle w10: c5363.72,2668.68 r16.58
  circle w10: c5363.72,2668.68 r27.63
  lines w10: 5336.09,2143.78 5363.72,2157.59 5391.34,2143.78 5377.53,2171.4 5391.34,2199.03 5363.72,2185.22 5336.09,2199.03 5349.9,2171.4 5336.09,2143.78 ; 5336.09,2281.91 5349.9,2281.91 5349.9,2268.1 5377.53,2268.1 5377.53,2281.91 5391.34,2281.91 5391.34,2309.54 5377.53,2309.54 5377.53,2323.35 5349.9,2323.35 5349.9,2309.54 5336.09,2309.54 5336.09,2281.91 ; 5336.09,2447.67 5391.34,2447.67 5363.72,2392.42 5336.09,2447.67 ; 5336.09,2530.55 5349.9,2530.55 5363.72,2516.74 5377.53,2530.55 5391.34,2530.55 5377.53,2544.36 5391.34,2558.18 5377.53,2558.18 5363.72,2571.99 5349.9,2558.18 5336.09,2558.18 5349.9,2544.36 5336.09,2530.55 ; 5336.09,2765.38 5336.09,2779.19 5349.9,2793 5336.09,2806.82 5336.09,2820.63 5349.9,2820.63 5363.72,2806.82 5377.53,2820.63 5391.34,2820.63 5391.34,2806.82 5377.53,2793 5391.34,2779.19 5391.34,2765.38 5377.53,2765.38 5363.72,2779.19 5349.9,2765.38 5336.09,2765.38 ; 5336.09,2917.32 5363.72,2889.7 5391.34,2917.32 5363.72,2944.95 5336.09,2917.32 ; 5336.09,3138.34 5391.34,3138.34 5391.34,3193.59 5336.09,3193.59 5336.09,3138.34 ; 5336.09,3317.91 5391.34,3317.91 5363.72,3262.66 5336.09,3317.91 ; 5347.14,3149.39 5380.29,3149.39 5380.29,3182.54 5347.14,3182.54 5347.14,3149.39 ; 5347.14,3306.86 5380.29,3306.86 5363.72,3273.71 5347.14,3306.86
  lines w12: 5286,2106.48 8517.49,2106.48 ; 5286,3349.68 8517.49,3349.68 ; 5623.86,1982.16 5623.86,3474 ; 5955.86,1982.16 5955.86,3474 ; 6592.43,1982.16 6592.43,3474 ; 6851.57,1982.16 6851.57,3474 ; 7226.72,1982.16 7226.72,3474 ; 7951.05,1982.16 7951.05,3474 ; 5286,1982.16 8517.49,1982.16 8517.49,3474 5286,3474 5286,1982.16
  text "Symbol" at 5360.59,3386.98 h72
  text "Quantity" at 5661.16,3386.98 h72
  text "Finished Hole Size" at 5993.16,3386.98 h72
  text "Plated" at 6629.72,3386.98 h72
  text "Hole Type" at 6888.86,3386.98 h72
  text "Drill Layer Pair" at 7264.02,3386.98 h72
  text "Hole Tolerance" at 7988.35,3386.98 h72
  text "4" at 5661.16,3262.66 h60
  text "125.98mil (3.200mm)" at 5993.16,3262.66 h60
  text "NPTH" at 6629.72,3262.66 h60
  text "Round" at 6888.86,3262.66 h60
  text "Top Layer - Bottom Layer" at 7264.02,3262.66 h60
  text "26" at 5661.16,3138.34 h60
  text "7.87mil (0.200mm)" at 5993.16,3138.34 h60
  text "PTH" at 6629.72,3138.34 h60
  text "Round" at 6888.86,3138.34 h60
  text "Top Layer - Bottom Layer" at 7264.02,3138.34 h60
  text "332" at 5661.16,3014.02 h60
  text "10.00mil (0.254mm)" at 5993.16,3014.02 h60
  text "PTH" at 6629.72,3014.02 h60
  text "Round" at 6888.86,3014.02 h60
  text "Top Layer - Bottom Layer" at 7264.02,3014.02 h60
  text "20" at 5661.16,2889.7 h60
  text "33.07mil (0.840mm)" at 5993.16,2889.7 h60
  text "PTH" at 6629.72,2889.7 h60
  text "Round" at 6888.86,2889.7 h60
  text "Top Layer - Bottom Layer" at 7264.02,2889.7 h60
  text "13" at 5661.16,2765.38 h60
  text "40.00mil (1.016mm)" at 5993.16,2765.38 h60
  text "PTH" at 6629.72,2765.38 h60
  text "Round" at 6888.86,2765.38 h60
  text "Top Layer - Bottom Layer" at 7264.02,2765.38 h60
  text "4" at 5661.16,2641.06 h60
  text "40.16mil (1.020mm)" at 5993.16,2641.06 h60
  text "PTH" at 6629.72,2641.06 h60
  text "Round" at 6888.86,2641.06 h60
  text "Top Layer - Bottom Layer" at 7264.02,2641.06 h60
  text "10" at 5661.16,2516.74 h60
  text "49.21mil (1.250mm)" at 5993.16,2516.74 h60
  text "PTH" at 6629.72,2516.74 h60
  text "Round" at 6888.86,2516.74 h60
  text "Top Layer - Bottom Layer" at 7264.02,2516.74 h60
  text "1" at 5661.16,2392.42 h60
  text "52.00mil (1.321mm)" at 5993.16,2392.42 h60
  text "PTH" at 6629.72,2392.42 h60
  text "Round" at 6888.86,2392.42 h60
  text "Top Layer - Bottom Layer" at 7264.02,2392.42 h60
  text "6" at 5661.16,2268.1 h60
  text "63.00mil (1.600mm)" at 5993.16,2268.1 h60
  text "PTH" at 6629.72,2268.1 h60
  text "Round" at 6888.86,2268.1 h60
  text "Top Layer - Bottom Layer" at 7264.02,2268.1 h60
  text "6" at 5661.16,2143.78 h60
  text "98.43mil (2.500mm)" at 5993.16,2143.78 h60
  text "PTH" at 6629.72,2143.78 h60
  text "Round" at 6888.86,2143.78 h60
  text "Top Layer - Bottom Layer" at 7264.02,2143.78 h60
  text "422 Total" at 5661.16,2019.46 h60
  text ".Layer_Name" at 577,-858.49 h60
M17 Embedded Cavity:
  text ".Layer_Name" at 577,-858.49 h60
M18 Embedded Assembly:
  text ".Layer_Name" at 577,-858.49 h60
M19 Embedded Keepout:
  text ".Layer_Name" at 577,-858.49 h60

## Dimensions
0,-400 to 1000,-400 on M2 Board Dimensions
0,0 to 0,4000 on M2 Board Dimensions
